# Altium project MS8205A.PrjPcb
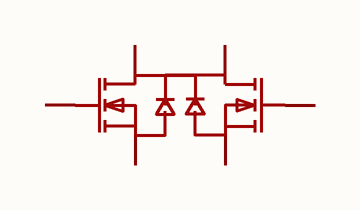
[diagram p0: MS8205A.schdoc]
1 sheet, 1 parts. Net scope: global (net labels, ports and power ports of the same name join across sheets).

## Sheet MS8205A.schdoc
size 127 x 101 mm

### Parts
Q?  ms8205a  [SOT-23-6_L2.9-W1.6-P0.95-LS2.8-BL]  (value not drawn)

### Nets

Not connected (* = marked no-connect by the designer): Q? 1(S) 2(D) 3(S) 4(G) 5(D) 6(G)

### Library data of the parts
Q? = ms8205a: 数量:2个N沟道;漏源电压(Vdss):20V;连续漏极电流(Id):6A;导通电阻(RDS(on)):22mΩ@4.5V；26mΩ@2.5V;耗散功率(Pd):1.25W;阈值电压(Vgs(th)):700mV;; Manufacturer: MSKSEMI(美森科); AddInBom: yes; ModelId: 18da8f6c14a34920b3e136b5c401a119; ModelName: SOT-23-6_L2.9-W1.6-H1.5-LS2.8-P0.95; ModelTransform: 110.236,113.364,0,90,0,0,0.0005,0.0005,0; Number: 2个N沟道; Drain to Source Voltage: 20V; Current - Continuous Drain(Id): 6A; Pd - Power Dissipation: 1.25W; Gate Threshold Voltage (Vgs(th)): 700mV; Gate Charge(Qg): 11nC@4.5V; Input Capacitance(Ciss): 600pF; Reverse Transfer Capacitance (Crss@Vds): 140pF; Type: N沟道; Output Capacitance(Coss): 330pF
